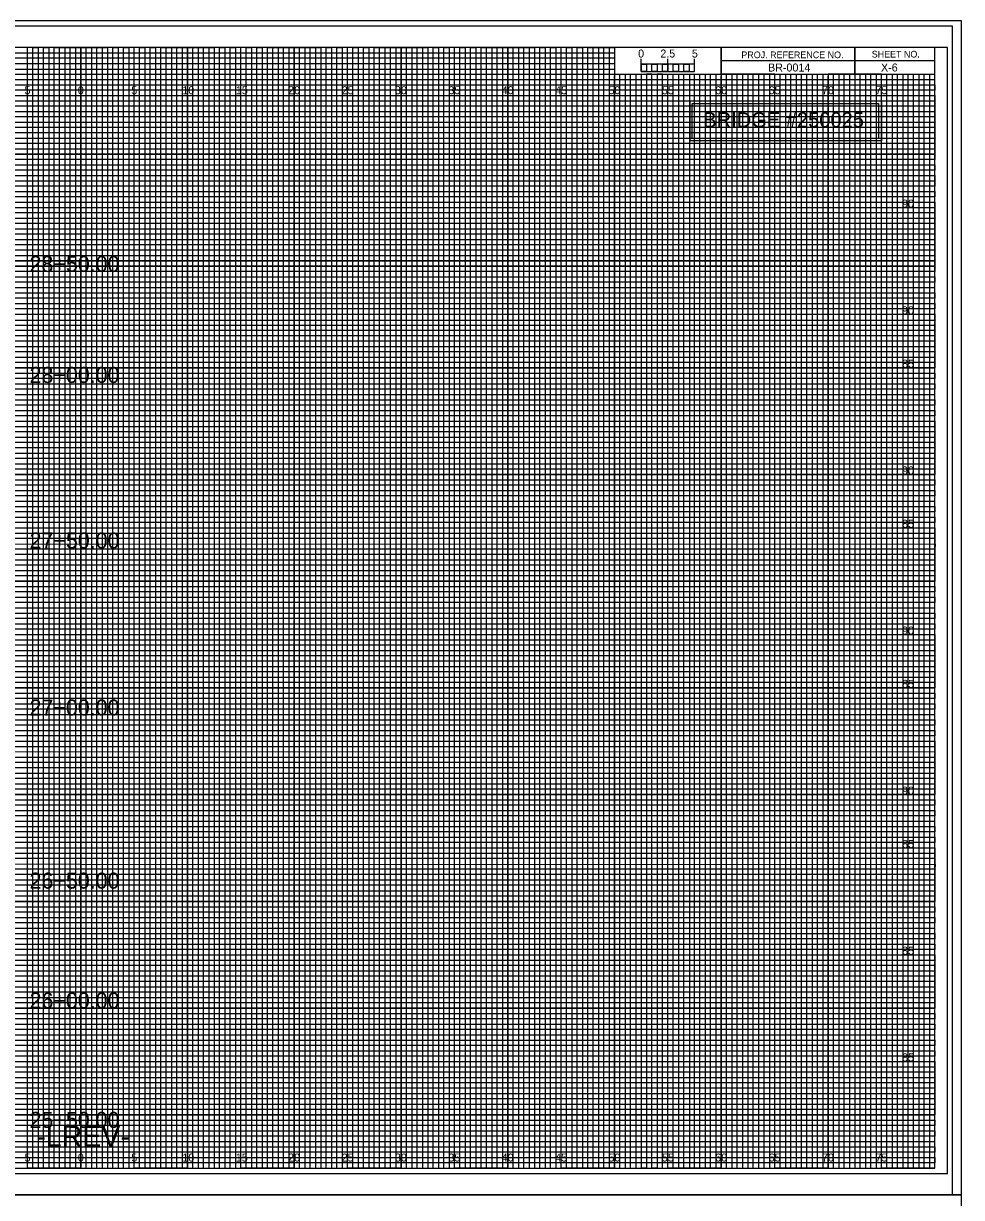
# Model space of a CAD drawing. Extents: x -8 to 533, y -20 to 768.
# Drawn here: x 74.6 to 162.5, y 547.2 to 657.2 of the extents above; entities that cross this region are included whole.
import ezdxf

# ---------------------------------------------------------------- set-up
doc = ezdxf.new("R2010")
doc.units = 0
for name, color, linetype in [('Old_Level_1', 7, 'Continuous'), ('Old_Level_34', 7, 'Continuous'), ('Prop Grid Mask', 7, 'Continuous'), ('Prop XS Alignment Label', 7, 'Continuous'), ('Prop XS Bar Scale Labels', 7, 'Continuous'), ('Prop XS Elevation Labels', 7, 'Continuous'), ('Prop XS Offset Labels', 7, 'Continuous'), ('Prop XS Project Number', 7, 'Continuous'), ('Prop XS Sheet Number', 7, 'Continuous'), ('Prop XS Station Labels', 7, 'Continuous'), ('Sheet Cross Section CELL', 7, 'Continuous'), ('Sheet Cross Section Grid Major CELL', 7, 'Continuous'), ('Sheet Cross Section Grid Middle CELL', 7, 'Continuous'), ('Sheet Cross Section Grid Minor 1 CELL', 7, 'Continuous'), ('Sheet Cross Section Grid Minor 2 CELL', 7, 'Continuous'), ('Sheet Cross Section Scale CELL', 7, 'Continuous'), ('Sheet Cutting Line CELL', 7, 'Continuous'), ('Sheet DOT Grid CELL', 7, 'Continuous'), ('Sheet Plot Border Inside CELL', 7, 'Continuous'), ('Sheet Plot Border Outside CELL', 7, 'Continuous'), ('WEI Plot Border', 7, 'Continuous')]:
    doc.layers.add(name, color=color, linetype=linetype)

msp = doc.modelspace()

# ---------------------------------------------------------------- linework, layer by layer
at = {"layer": 'Old_Level_34'}
msp.add_lwpolyline([(137.26, 649.75), (154.74, 649.75), (154.74, 646.46), (137.26, 646.46)], close=True, dxfattribs=at)
at = {"layer": 'Prop Grid Mask'}
msp.add_lwpolyline([(137.08, 650), (155, 650), (155, 646.24), (137.08, 646.24)], close=True, dxfattribs=at)
at = {"layer": 'Sheet Cross Section CELL'}
for p, q in [((152.5, 655), (152.5, 652.5)), ((152.5, 652.5), (152.5, 655)), ((160, 653.75), (140, 653.75)), ((140, 653.75), (140, 652.5)), ((140, 652.5), (160, 652.5))]:
    msp.add_line(p, q, dxfattribs=at)
for points in [[(160, 655), (0, 655), (0, 550), (160, 550)], [(140, 655), (130, 655), (130, 652.51), (140, 652.51)], [(160, 655), (140, 655), (140, 652.5), (160, 652.5)]]:
    msp.add_lwpolyline(points, close=True, dxfattribs=at)
at = {"layer": 'Sheet Cross Section Grid Major CELL'}
for p, q in [((75, 655), (70, 655)), ((75, 550), (75, 655)), ((85, 655), (80, 655)), ((80, 655), (80, 550)), ((85, 550), (85, 655)), ((95, 655), (90, 655)), ((90, 655), (90, 550)), ((95, 550), (95, 655)), ((105, 655), (100, 655)), ((100, 655), (100, 550)), ((105, 550), (105, 655)), ((115, 655), (110, 655)), ((110, 655), (110, 550)), ((115, 550), (115, 655)), ((125, 655), (120, 655)), ((120, 655), (120, 550)), ((125, 550), (125, 655)), ((130, 655), (130, 550)), ((135, 550), (135, 652.5)), ((145, 652.5), (140, 652.5)), ((140, 652.5), (140, 550)), ((145, 550), (145, 652.5)), ((155, 652.5), (150, 652.5)), ((150, 652.5), (150, 550)), ((155, 550), (155, 652.5)), ((80, 550), (75, 550)), ((90, 550), (85, 550)), ((100, 550), (95, 550)), ((110, 550), (105, 550)), ((120, 550), (115, 550)), ((130, 550), (125, 550)), ((140, 550), (135, 550)), ((150, 550), (145, 550)), ((160, 550), (155, 550)), ((160, 550), (160, 550))]:
    msp.add_line(p, q, dxfattribs=at)
for points in [[(0, 650), (160, 650), (160, 645), (0, 645)], [(0, 640), (160, 640), (160, 635), (0, 635)], [(0, 630), (160, 630), (160, 625), (0, 625)], [(0, 620), (160, 620), (160, 615), (0, 615)], [(0, 610), (160, 610), (160, 605), (0, 605)], [(0, 600), (160, 600), (160, 595), (0, 595)], [(0, 590), (160, 590), (160, 585), (0, 585)], [(0, 580), (160, 580), (160, 575), (0, 575)], [(0, 570), (160, 570), (160, 565), (0, 565)], [(0, 560), (160, 560), (160, 555), (0, 555)]]:
    msp.add_lwpolyline(points, dxfattribs=at)
at = {"layer": 'Sheet Cross Section Grid Middle CELL'}
for points in [[(72.5, 550), (77.5, 550), (77.5, 655), (82.5, 655), (82.5, 550), (87.5, 550), (87.5, 655), (92.5, 655), (92.5, 550), (97.5, 550), (97.5, 655), (102.5, 655), (102.5, 550), (107.5, 550), (107.5, 655), (112.5, 655), (112.5, 550), (117.5, 550), (117.5, 655), (122.5, 655), (122.5, 550), (127.5, 550), (127.5, 655), (129.97, 655), (130, 655), (130, 652.5), (132.5, 652.5), (132.5, 550), (137.5, 550), (137.5, 652.5), (142.5, 652.5), (142.5, 550), (147.5, 550), (147.5, 652.5), (152.5, 652.5), (152.5, 550), (157.5, 550), (157.5, 652.5)], [(0, 652.5), (137.5, 652.5)], [(0, 642.5), (160, 642.5), (160, 647.5), (0, 647.5)], [(0, 632.5), (160, 632.5), (160, 637.5), (0, 637.5)], [(0, 622.5), (160, 622.5), (160, 627.5), (0, 627.5)], [(0, 612.5), (160, 612.5), (160, 617.5), (0, 617.5)], [(0, 602.5), (160, 602.5), (160, 607.5), (0, 607.5)], [(0, 592.5), (160, 592.5), (160, 597.5), (0, 597.5)], [(0, 582.5), (160, 582.5), (160, 587.5), (0, 587.5)], [(0, 572.5), (160, 572.5), (160, 577.5), (0, 577.5)], [(0, 562.5), (160, 562.5), (160, 567.5), (0, 567.5)], [(0, 552.5), (160, 552.5), (160, 557.5), (0, 557.5)]]:
    msp.add_lwpolyline(points, dxfattribs=at)
at = {"layer": 'Sheet Cross Section Grid Minor 1 CELL'}
for p, q in [((0, 654.5), (130, 654.5)), ((130, 654.5), (130, 653.99)), ((130, 653.99), (0, 653.99)), ((0, 653.5), (130, 653.5)), ((130, 653.5), (130, 652.95)), ((130, 652.95), (0, 652.95)), ((0, 652), (160, 652))]:
    msp.add_line(p, q, dxfattribs=at)
for points in [[(0, 651.5), (135, 651.5), (160, 651.5), (160, 651), (0, 651)], [(0, 650.5), (160, 650.5), (160, 649.5), (0, 649.5)], [(0, 649), (160, 649), (160, 648.5), (0, 648.49)], [(0, 648), (160, 648), (160, 647), (0, 647)], [(0, 646.5), (160, 646.5), (160, 646), (0, 646)], [(0, 645.5), (160, 645.5), (160, 644.5), (0, 644.5)], [(0, 644), (160, 644), (160, 643.5), (0, 643.5)], [(0, 643), (160, 643), (160, 642), (0, 642)], [(0, 641.5), (160, 641.5), (160, 641), (0, 641)], [(0, 640.5), (160, 640.5), (160, 639.5), (0, 639.5)], [(0, 639), (160, 639), (160, 638.5), (0, 638.5)], [(0, 638), (160, 638), (160, 636.98), (160, 636.5), (160, 636), (0, 636)], [(0, 637), (160, 637), (160, 636.5), (0, 636.5)], [(0, 635.5), (160, 635.5), (160, 634.5), (0, 634.51)], [(0, 634.51), (160, 634.5), (160, 634), (0, 634)], [(0, 633.5), (160, 633.5), (160, 633), (0, 633)], [(0, 632), (160, 632), (160, 631.5), (0, 631.5)], [(0, 631), (160, 631), (160, 630.5), (0, 630.5)], [(-0.04, 629.45), (160, 629.45), (160, 628.94), (-0.04, 628.94)], [(0, 628.5), (160, 628.5), (160, 628), (0, 628)], [(0, 627), (160, 627), (160, 626.5), (0, 626.5)], [(0, 626), (160, 626), (160, 625.5), (0, 625.5)], [(0, 624.5), (160, 624.5), (160, 624), (0, 624)], [(0, 623.5), (160, 623.5), (160, 623), (0, 623)], [(0, 622), (160, 622), (160, 621.5), (0, 621.5)], [(0, 621), (160, 621), (160, 620.5), (0, 620.5)], [(0, 619.5), (160, 619.5), (160, 618.99), (0, 619)], [(0, 618.5), (160, 618.5), (160, 618), (0, 618)], [(0, 617), (160, 617), (160, 616.5), (0, 616.5)], [(0, 616), (160, 616), (160, 615.5), (0, 615.5)], [(0, 614.5), (160, 614.5), (160, 614), (0, 614)], [(0, 613.5), (160, 613.5), (160, 613), (0, 613)], [(0, 612), (160, 612), (160, 611.5), (0, 611.5)], [(0, 611), (160, 611), (160, 610.5), (0, 610.5)], [(0, 609.5), (160, 609.5), (160, 609), (0, 609)], [(0, 608.5), (160.03, 608.46), (160, 608), (0, 608)], [(0, 607), (160, 607), (160, 606.5), (0, 606.5)], [(0, 606), (160, 606), (160, 605.5), (0, 605.5)], [(0, 604.5), (160, 604.5), (160, 604), (0, 604)], [(0, 603.5), (160, 603.5), (160, 603), (0, 603)], [(0, 602), (160, 602), (160, 601.5), (0, 601.5)], [(0, 601), (160, 601), (160, 600.5), (0, 600.5)], [(0, 599.5), (160, 599.5), (160, 599), (0, 599)], [(0, 598.5), (160, 598.5), (160, 598), (0, 598)], [(0, 597), (160, 597), (160, 596.5), (0, 596.5)], [(0, 596), (160, 596), (160, 595.5), (0, 595.5)], [(0, 594.5), (160, 594.5), (160, 594), (0, 594)], [(0, 593.5), (160, 593.5), (160, 593), (0, 593)], [(0, 592), (160, 592), (160, 591.5), (0, 591.5)], [(0, 591), (160, 591), (160, 590.5), (0, 590.5)], [(0, 589.5), (160, 589.5), (160, 588.99), (0, 589)], [(0, 588.5), (160, 588.5), (160, 588), (0, 588)], [(0, 587), (160, 587), (160, 586.5), (0, 586.5)], [(0, 586), (160, 586), (160, 585.5), (0, 585.5)], [(0, 584.5), (160, 584.5), (160, 584), (0, 584)], [(0, 583.5), (160, 583.5), (160, 583), (0, 583)], [(0, 582), (160, 582), (160, 581.5), (0, 581.5)], [(0, 581), (160, 581), (160, 580.5), (0, 580.5)], [(0, 579.5), (160, 579.5), (160, 579), (0, 579)], [(0, 578.5), (160.03, 578.46), (160, 578), (0, 578)], [(0, 577), (160, 577), (160, 576.5), (0, 576.5)], [(0, 576), (160, 576), (160, 575.5), (0, 575.5)], [(0, 574.5), (160, 574.5), (160, 574), (0, 574)], [(0, 573.5), (160, 573.5), (160, 573), (0, 573)], [(0, 572), (160, 572), (160, 571.5), (0, 571.5)], [(0, 571), (160, 571), (160, 570.5), (0, 570.5)], [(0, 569.5), (160, 569.5), (160, 569), (0, 569)], [(0, 568.5), (160, 568.5), (160, 568), (0, 568)], [(0, 567), (160, 567), (160, 566.5), (0, 566.5)], [(0, 566), (160, 566), (160, 565.5), (0, 565.5)], [(0, 564.5), (160, 564.5), (160, 564), (0, 564)], [(0, 563.5), (160, 563.5), (160, 563), (0, 563)], [(0, 562), (160, 562), (160, 561.5), (0, 561.5)], [(0, 561), (160, 561), (160, 560.5), (0, 560.5)], [(0, 559.5), (160, 559.5), (160, 559), (0, 559)], [(0, 558.5), (160, 558.5), (160, 558), (0, 558)], [(0, 557), (160, 557), (160, 556.5), (0, 556.5)], [(0, 556), (160, 556), (160, 555.5), (0, 555.5)], [(0, 554.5), (160, 554.5), (160, 554), (0, 554)], [(0, 553.5), (160, 553.5), (160, 553), (0, 553)], [(0, 552), (160, 552), (160, 551.5), (0, 551.5)], [(0, 551), (160, 551), (160, 550.5), (0, 550.5)]]:
    msp.add_lwpolyline(points, dxfattribs=at)
at = {"layer": 'Sheet Cross Section Grid Minor 2 CELL'}
for p, q in [((133.5, 652.5), (133, 652.5)), ((133, 652.5), (133, 550)), ((133.5, 550), (133.5, 652.5)), ((134.5, 652.5), (134, 652.5)), ((134, 652.5), (134, 550)), ((134.5, 550), (134.5, 652.5)), ((133, 550), (132.5, 550)), ((134, 550), (133.5, 550))]:
    msp.add_line(p, q, dxfattribs=at)
for points in [[(75, 550), (75.5, 550), (75.5, 655), (76, 655), (76, 550)], [(76, 550), (76.5, 550), (76.5, 655), (77, 655), (77, 550)], [(77.5, 550), (78, 550), (78, 655), (78.5, 655), (78.5, 550)], [(78.5, 550), (79, 550), (79, 655), (79.5, 655), (79.5, 550)], [(80, 550), (80.5, 550), (80.5, 655), (81, 655), (81, 550)], [(81, 550), (81.5, 550), (81.5, 655), (82, 655), (82, 550)], [(82.5, 550), (83, 550), (83, 655), (83.5, 655), (83.5, 550)], [(83.5, 550), (84, 550), (84, 655), (84.5, 655), (84.5, 550)], [(85, 550), (85.5, 550), (85.5, 655), (86, 655), (86, 550)], [(86, 550), (86.5, 550), (86.5, 655), (87, 655), (87, 550)], [(87.5, 550), (88, 550), (88, 655), (88.5, 655), (88.5, 550)], [(88.5, 550), (89, 550), (89, 655), (89.5, 655), (89.5, 550)], [(90, 550), (90.5, 550), (90.5, 655), (91, 655), (91, 550)], [(91, 550), (91.5, 550), (91.5, 655), (92, 655), (92, 550)], [(92.5, 550), (93, 550), (93, 655), (93.5, 655), (93.5, 550)], [(93.5, 550), (94, 550), (94, 655), (94.5, 655), (94.5, 550)], [(95, 550), (95.5, 550), (95.5, 655), (96, 655), (96, 550)], [(96, 550), (96.5, 550), (96.5, 655), (97, 655), (97, 550)], [(97.5, 550), (98, 550), (98, 655), (98.5, 655), (98.5, 550)], [(98.5, 550), (99, 550), (99, 655), (99.5, 655), (99.5, 550)], [(100, 550), (100.5, 550), (100.5, 655), (101, 655), (101, 550)], [(101, 550), (101.5, 550), (101.5, 655), (102, 655), (102, 550)], [(102.5, 550), (103, 550), (103, 655), (103.5, 655), (103.5, 550)], [(103.5, 550), (104, 550), (104, 655), (104.5, 655), (104.5, 550)], [(105, 550), (105.5, 550), (105.5, 655), (106, 655), (106, 550)], [(106, 550), (106.5, 550), (106.5, 655), (107, 655), (107, 550)], [(107.5, 550), (108, 550), (108, 655), (108.5, 655), (108.5, 550)], [(108.5, 550), (109, 550), (109, 655), (109.5, 655), (109.5, 550)], [(110, 550), (110.5, 550), (110.5, 655), (111, 655), (111, 550)], [(111, 550), (111.5, 550), (111.5, 655), (112, 655), (112, 550)], [(112.5, 550), (113, 550), (113, 655), (113.5, 655), (113.5, 550)], [(113.5, 550), (114, 550), (114, 655), (114.5, 655), (114.5, 550)], [(115, 550), (115.5, 550), (115.5, 655), (116, 655), (116, 550)], [(116, 550), (116.5, 550), (116.5, 655), (117, 655), (117, 550)], [(117.5, 550), (118, 550), (118, 655), (118.5, 655), (118.5, 550)], [(118.5, 550), (119, 550), (119, 655), (119.5, 655), (119.5, 550)], [(120, 550), (120.5, 550), (120.5, 655), (121, 655), (121, 550)], [(121, 550), (121.5, 550), (121.5, 655), (122, 655), (122, 550)], [(122.5, 550), (123, 550), (123, 655), (123.5, 655), (123.5, 550)], [(123.5, 550), (124, 550), (124, 655), (124.5, 655), (124.5, 550)], [(125, 550), (125.5, 550), (125.5, 655), (126, 655), (126, 550)], [(126, 550), (126.5, 550), (126.5, 655), (127, 655), (127, 550)], [(127.5, 550), (128, 550), (128, 655), (128.5, 655), (128.5, 550)], [(128.5, 550), (129, 550), (129, 655), (129.5, 655), (129.5, 550)], [(130, 550), (130.5, 550), (130.5, 652.5), (131.01, 652.5), (131.01, 550)], [(131, 550), (131.5, 550), (131.5, 652.5), (132, 652.5), (132, 550)], [(135, 550), (135.49, 550), (135.49, 652.5), (136, 652.5), (136, 550)], [(136, 550), (136.5, 550), (136.5, 652.5), (137.03, 652.5), (137.03, 550)], [(137.5, 550), (138, 550), (138, 652.5), (138.5, 652.5), (138.5, 550)], [(138.5, 550), (139, 550), (139, 652.5), (139.5, 652.5), (139.5, 550)], [(140, 550), (140.5, 550), (140.5, 652.5), (141, 652.5), (141, 550)], [(141, 550), (141.5, 550), (141.5, 652.5), (142, 652.5), (142, 550)], [(142.5, 550), (143, 550), (143, 652.5), (143.5, 652.5), (143.5, 550)], [(143.5, 550), (144, 550), (144, 652.5), (144.5, 652.5), (144.5, 550)], [(145, 550), (145.5, 550), (145.5, 652.5), (146, 652.5), (146, 550)], [(146, 550), (146.5, 550), (146.5, 652.5), (147, 652.5), (147, 550)], [(147.5, 550), (148, 550), (148, 652.5), (148.5, 652.5), (148.5, 550)], [(148.5, 550), (149, 550), (149, 652.5), (149.5, 652.5), (149.5, 550)], [(150, 550), (150.5, 550), (150.5, 652.5), (151, 652.5), (151, 550)], [(151, 550), (151.5, 550), (151.5, 652.5), (152, 652.5), (152, 550)], [(152.5, 550), (153, 550), (153, 652.5), (153.5, 652.5), (153.5, 550)], [(153.5, 550), (154, 550), (154, 652.5), (154.5, 652.5), (154.5, 550)], [(155, 550), (155.5, 550), (155.5, 652.5), (156, 652.5), (156, 550)], [(156, 550), (156.5, 550), (156.5, 652.5), (157, 652.5), (157, 550)], [(157.5, 550), (158, 550), (158, 652.5), (158.5, 652.5), (158.5, 550)], [(158.5, 550), (159, 550), (159, 652.5), (159.5, 652.5), (159.5, 550)]]:
    msp.add_lwpolyline(points, dxfattribs=at)
at = {"layer": 'Sheet Cross Section Scale CELL'}
for p, q in [((132.5, 652.75), (132.5, 653.95)), ((132.5, 653.45), (132.5, 653.95)), ((135, 652.75), (135, 653.95)), ((137.5, 652.75), (137.5, 653.95)), ((137.5, 653.45), (137.5, 653.95))]:
    msp.add_line(p, q, dxfattribs=at)
for points in [[(137.5, 653.45), (132.5, 653.45), (132.5, 652.75), (137.5, 652.75)], [(132.5, 653.45), (133, 653.45), (133, 652.75), (132.5, 652.75)], [(133.5, 653.45), (134, 653.45), (134, 652.75), (133.5, 652.75)], [(134.5, 653.45), (135, 653.45), (135, 652.75), (134.5, 652.75)], [(135.5, 653.45), (136, 653.45), (136, 652.75), (135.5, 652.75)], [(136.5, 653.45), (137, 653.45), (137, 652.75), (136.5, 652.75)]]:
    msp.add_lwpolyline(points, close=True, dxfattribs=at)
at = {"layer": 'Sheet Cutting Line CELL'}
for p, q in [((161.65, 657), (-6.7, 657)), ((-6.7, 547.5), (161.65, 547.5))]:
    msp.add_line(p, q, dxfattribs=at)
at = {"layer": 'Sheet DOT Grid CELL'}
for p, q in [((75, 550), (75, 655)), ((80, 550), (80, 655)), ((85, 550), (85, 655)), ((90, 550), (90, 655)), ((95, 550), (95, 655)), ((100, 550), (100, 655)), ((105, 550), (105, 655)), ((110, 550), (110, 655)), ((115, 550), (115, 655)), ((120, 550), (120, 655)), ((125, 550), (125, 655)), ((130, 550), (130, 652.34)), ((135, 550), (135, 652.34)), ((140, 550), (140, 652.34)), ((145, 550), (145, 652.34)), ((150, 550), (150, 652.34)), ((155, 550), (155, 652.34)), ((0, 650), (160, 650)), ((0, 645), (160, 645)), ((0, 640), (160, 640)), ((0, 635), (160, 635)), ((0, 630), (160, 630)), ((0, 625), (160, 625)), ((0, 620), (160, 620)), ((0, 615), (160, 615)), ((0, 610), (160, 610)), ((0, 605), (160, 605)), ((0, 600), (160, 600)), ((0, 595), (160, 595)), ((0, 590), (160, 590)), ((0, 585), (160, 585)), ((0, 580), (160, 580)), ((0, 575), (160, 575)), ((0, 570), (160, 570)), ((0, 565), (160, 565)), ((0, 560), (160, 560)), ((0, 555), (160, 555))]:
    msp.add_line(p, q, dxfattribs=at)
at = {"layer": 'Sheet Plot Border Inside CELL'}
msp.add_lwpolyline([(-5.4, 549.5), (161.2, 549.5), (161.2, 655), (-5.4, 655)], close=True, dxfattribs=at)
at = {"layer": 'Sheet Plot Border Outside CELL'}
msp.add_lwpolyline([(-6.7, 547.5), (161.65, 547.5), (161.65, 657), (-6.7, 657)], close=True, dxfattribs=at)
at = {"layer": 'WEI Plot Border'}
for points in [[(-7.5, 547.5), (162.5, 547.5), (162.5, 657.5), (-7.5, 657.5)], [(-7.5, 437.5), (162.5, 437.5), (162.5, 547.5), (-7.5, 547.5)]]:
    msp.add_lwpolyline(points, close=True, dxfattribs=at)

# ---------------------------------------------------------------- texts
at = {"layer": 'Old_Level_1'}
msp.add_text('BRIDGE #250025', height=1.4062, rotation=360, dxfattribs=at).set_placement((138.31, 647.52))
at = {"layer": 'Prop XS Alignment Label'}
msp.add_text('-LREV-', height=2, dxfattribs=at).set_placement((75.84, 552))
at = {"layer": 'Prop XS Bar Scale Labels'}
for s, p in [('2.5', (134.29, 654.06)), ('5', (137.24, 654.06))]:
    msp.add_text(s, height=0.75, dxfattribs=at).set_placement(p)
at = {"layer": 'Prop XS Elevation Labels'}
for s, p in [('90', (156.93, 640)), ('90', (156.93, 630)), ('85', (156.94, 625)), ('90', (156.93, 615)), ('85', (156.94, 610)), ('90', (156.93, 600)), ('85', (156.94, 595)), ('90', (156.93, 585)), ('85', (156.94, 580)), ('85', (156.94, 570)), ('85', (156.94, 560))]:
    msp.add_text(s, height=0.75, dxfattribs=at).set_placement(p)
at = {"layer": 'Prop XS Offset Labels'}
for s, p in [('5', (74.74, 650.62)), ('0', (79.73, 650.62)), ('0', (79.73, 650.62)), ('5', (84.74, 650.62)), ('10', (89.52, 650.62)), ('15', (94.53, 650.62)), ('20', (99.43, 650.62)), ('25', (104.44, 650.62)), ('30', (109.43, 650.62)), ('35', (114.44, 650.62)), ('40', (119.43, 650.62)), ('45', (124.44, 650.62)), ('50', (129.43, 650.62)), ('55', (134.44, 650.62)), ('60', (139.43, 650.62)), ('65', (144.44, 650.62)), ('70', (149.43, 650.62)), ('75', (154.44, 650.62)), ('5', (74.74, 550.62)), ('0', (79.73, 550.62)), ('0', (79.73, 550.62)), ('5', (84.74, 550.62)), ('10', (89.52, 550.62)), ('15', (94.53, 550.62)), ('20', (99.43, 550.62)), ('25', (104.44, 550.62)), ('30', (109.43, 550.62)), ('35', (114.44, 550.62)), ('40', (119.43, 550.62)), ('45', (124.44, 550.62)), ('50', (129.43, 550.62)), ('55', (134.44, 550.62)), ('60', (139.43, 550.62)), ('65', (144.44, 550.62)), ('70', (149.43, 550.62)), ('75', (154.44, 550.62))]:
    msp.add_text(s, height=0.75, dxfattribs=at).set_placement(p)
at = {"layer": 'Prop XS Project Number'}
msp.add_text('BR-0014', height=0.75, dxfattribs=at).set_placement((144.38, 652.75))
at = {"layer": 'Prop XS Sheet Number'}
msp.add_text('X-6', height=0.75, dxfattribs=at).set_placement((154.96, 652.75))
at = {"layer": 'Prop XS Station Labels'}
for s, p in [('28+50.00', (75.21, 633.97)), ('28+00.00', (75.21, 623.57)), ('27+50.00', (75.21, 608.06)), ('27+00.00', (75.21, 592.41)), ('26+50.00', (75.21, 576.19)), ('26+00.00', (75.21, 564.96)), ('25+50.00', (75.21, 553.77))]:
    msp.add_text(s, height=1.5, dxfattribs=at).set_placement(p)
at = {"layer": 'Sheet Cross Section CELL'}
for s, p in [('PROJ. REFERENCE NO.', (141.88, 654)), ('SHEET NO.', (154.09, 654.06))]:
    msp.add_text(s, height=0.625, dxfattribs=at).set_placement(p)
at = {"layer": 'Sheet Cross Section Scale CELL'}
msp.add_text('0', height=0.75, dxfattribs=at).set_placement((132.21, 654.06))

doc.saveas('drawing.dxf')
